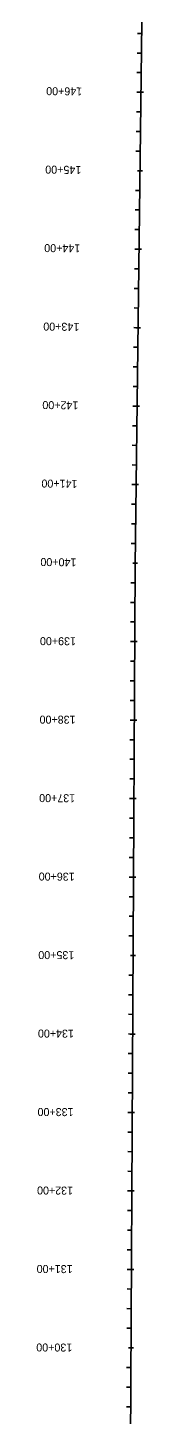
# Model space of a CAD drawing. Extents: x 17535628 to 17537899, y 7333852 to 7342653.
# Drawn here: x 17535638 to 17535774, y 7335599 to 7337366 of the extents above; entities that cross this region are included whole.
import ezdxf

# ---------------------------------------------------------------- set-up
doc = ezdxf.new("R2010")
doc.units = 0
for name, color, linetype in [('Alignment', 7, 'Continuous'), ('TextAlignmentLrg', 7, 'Continuous'), ('TextAlignmentSml', 7, 'Continuous')]:
    doc.layers.add(name, color=color, linetype=linetype)

msp = doc.modelspace()

# ---------------------------------------------------------------- linework, layer by layer
at = {"layer": 'Alignment'}
for p, q in [((17535763.4, 7336680.4), (17535771.9, 7337372.7)), ((17535748.4, 7333854.2), (17535763.4, 7336680.4))]:
    msp.add_line(p, q, dxfattribs=at)
at = {"layer": 'TextAlignmentLrg'}
for p, q in [((17535770.8, 7337283.3), (17535765.4, 7337283.3)), ((17535766.5, 7337183.3), (17535772.7, 7337183.2)), ((17535768.4, 7337083.3), (17535762.9, 7337083.4)), ((17535767.1, 7336983.3), (17535761.7, 7336983.4)), ((17535765.9, 7336883.3), (17535760.5, 7336883.4)), ((17535764.7, 7336783.3), (17535759.2, 7336783.4)), ((17535760.4, 7336683.4), (17535766.5, 7336683.3)), ((17535762.9, 7336583.3), (17535757.4, 7336583.3)), ((17535762.4, 7336483.3), (17535756.9, 7336483.3)), ((17535761.8, 7336383.3), (17535756.4, 7336383.3)), ((17535761.3, 7336283.3), (17535755.9, 7336283.3)), ((17535757.7, 7336183.3), (17535763.8, 7336183.3)), ((17535760.3, 7336083.3), (17535754.8, 7336083.4)), ((17535759.7, 7335983.3), (17535754.3, 7335983.4)), ((17535759.2, 7335883.3), (17535753.7, 7335883.4)), ((17535758.7, 7335783.3), (17535753.2, 7335783.4)), ((17535755.1, 7335683.3), (17535761.2, 7335683.3))]:
    msp.add_line(p, q, dxfattribs=at)
at = {"layer": 'TextAlignmentSml'}
for p, q in [((17535771.7, 7337358.3), (17535766.3, 7337358.3)), ((17535771.4, 7337333.3), (17535766, 7337333.3)), ((17535771.1, 7337308.3), (17535765.7, 7337308.3)), ((17535767.8, 7337283.3), (17535773.9, 7337283.2)), ((17535770.5, 7337258.3), (17535765.1, 7337258.3)), ((17535770.2, 7337233.3), (17535764.7, 7337233.3)), ((17535769.9, 7337208.3), (17535764.4, 7337208.3)), ((17535766.5, 7337183.3), (17535772.7, 7337183.2)), ((17535769.3, 7337158.3), (17535763.8, 7337158.3)), ((17535769, 7337133.3), (17535763.5, 7337133.3)), ((17535768.7, 7337108.3), (17535763.2, 7337108.3)), ((17535765.3, 7337083.3), (17535771.4, 7337083.2)), ((17535768.1, 7337058.3), (17535762.6, 7337058.4)), ((17535767.8, 7337033.3), (17535762.3, 7337033.4)), ((17535767.4, 7337008.3), (17535762, 7337008.4)), ((17535764.1, 7336983.3), (17535770.2, 7336983.3)), ((17535766.8, 7336958.3), (17535761.4, 7336958.4)), ((17535766.5, 7336933.3), (17535761.1, 7336933.4)), ((17535766.2, 7336908.3), (17535760.8, 7336908.4)), ((17535762.9, 7336883.3), (17535769, 7336883.3)), ((17535765.6, 7336858.3), (17535760.1, 7336858.4)), ((17535765.3, 7336833.3), (17535759.8, 7336833.4)), ((17535765, 7336808.3), (17535759.5, 7336808.4)), ((17535761.6, 7336783.3), (17535767.7, 7336783.3)), ((17535764.4, 7336758.3), (17535758.9, 7336758.4)), ((17535764.1, 7336733.3), (17535758.6, 7336733.4)), ((17535763.8, 7336708.3), (17535758.3, 7336708.4)), ((17535760.4, 7336683.4), (17535766.5, 7336683.3)), ((17535763.3, 7336658.3), (17535757.8, 7336658.3)), ((17535763.2, 7336633.3), (17535757.7, 7336633.3)), ((17535763, 7336608.3), (17535757.6, 7336608.3)), ((17535759.8, 7336583.3), (17535766, 7336583.3)), ((17535762.8, 7336558.3), (17535757.3, 7336558.3)), ((17535762.6, 7336533.3), (17535757.2, 7336533.3)), ((17535762.5, 7336508.3), (17535757.1, 7336508.3)), ((17535759.3, 7336483.3), (17535765.4, 7336483.3)), ((17535762.2, 7336458.3), (17535756.8, 7336458.3)), ((17535762.1, 7336433.3), (17535756.7, 7336433.3)), ((17535762, 7336408.3), (17535756.5, 7336408.3)), ((17535758.8, 7336383.3), (17535764.9, 7336383.3)), ((17535761.7, 7336358.3), (17535756.3, 7336358.3)), ((17535761.6, 7336333.3), (17535756.1, 7336333.3)), ((17535761.4, 7336308.3), (17535756, 7336308.3)), ((17535758.3, 7336283.3), (17535764.4, 7336283.3)), ((17535761.2, 7336258.3), (17535755.7, 7336258.3)), ((17535761.1, 7336233.3), (17535755.6, 7336233.3)), ((17535760.9, 7336208.3), (17535755.5, 7336208.3)), ((17535757.7, 7336183.3), (17535763.8, 7336183.3)), ((17535760.7, 7336158.3), (17535755.2, 7336158.3)), ((17535760.5, 7336133.3), (17535755.1, 7336133.4)), ((17535760.4, 7336108.3), (17535754.9, 7336108.4)), ((17535757.2, 7336083.3), (17535763.3, 7336083.3)), ((17535760.1, 7336058.3), (17535754.7, 7336058.4)), ((17535760, 7336033.3), (17535754.5, 7336033.4)), ((17535759.9, 7336008.3), (17535754.4, 7336008.4)), ((17535756.7, 7335983.3), (17535762.8, 7335983.3)), ((17535759.6, 7335958.3), (17535754.1, 7335958.4)), ((17535759.5, 7335933.3), (17535754, 7335933.4)), ((17535759.3, 7335908.3), (17535753.9, 7335908.4)), ((17535756.1, 7335883.3), (17535762.3, 7335883.3)), ((17535759.1, 7335858.3), (17535753.6, 7335858.4)), ((17535758.9, 7335833.3), (17535753.5, 7335833.4)), ((17535758.8, 7335808.3), (17535753.3, 7335808.4)), ((17535755.6, 7335783.3), (17535761.7, 7335783.3)), ((17535758.5, 7335758.3), (17535753.1, 7335758.4)), ((17535758.4, 7335733.3), (17535752.9, 7335733.4)), ((17535758.3, 7335708.3), (17535752.8, 7335708.4)), ((17535755.1, 7335683.3), (17535761.2, 7335683.3)), ((17535758, 7335658.3), (17535752.5, 7335658.4)), ((17535757.9, 7335633.3), (17535752.4, 7335633.4)), ((17535757.7, 7335608.3), (17535752.3, 7335608.4))]:
    msp.add_line(p, q, dxfattribs=at)

# ---------------------------------------------------------------- texts
at = {"layer": 'TextAlignmentLrg'}
for s, rotation, p in [('145+00', 179.2972, (17535694.7, 7337189.3)), ('140+00', 179.2972, (17535688.5, 7336689.3)), ('135+00', 179.6959, (17535685.8, 7336188.8)), ('130+00', 179.6959, (17535683.2, 7335688.8))]:
    msp.add_text(s, height=10.2, rotation=rotation, dxfattribs=at).set_placement(p)
at = {"layer": 'TextAlignmentSml'}
for s, rotation, p in [('146+00', 179.2972, (17535695.9, 7337289.3)), ('145+00', 179.2972, (17535694.7, 7337189.3)), ('144+00', 179.2972, (17535693.4, 7337089.3)), ('143+00', 179.2972, (17535692.2, 7336989.3)), ('142+00', 179.2972, (17535691, 7336889.3)), ('141+00', 179.2972, (17535689.8, 7336789.3)), ('140+00', 179.2972, (17535688.5, 7336689.3)), ('139+00', 179.6959, (17535687.9, 7336588.8)), ('138+00', 179.6959, (17535687.4, 7336488.8)), ('137+00', 179.6959, (17535686.9, 7336388.8)), ('136+00', 179.6959, (17535686.3, 7336288.8)), ('135+00', 179.6959, (17535685.8, 7336188.8)), ('134+00', 179.6959, (17535685.3, 7336088.8)), ('133+00', 179.6959, (17535684.8, 7335988.8)), ('132+00', 179.6959, (17535684.2, 7335888.8)), ('131+00', 179.6959, (17535683.7, 7335788.8)), ('130+00', 179.6959, (17535683.2, 7335688.8))]:
    msp.add_text(s, height=10.2, rotation=rotation, dxfattribs=at).set_placement(p)

doc.saveas('drawing.dxf')
